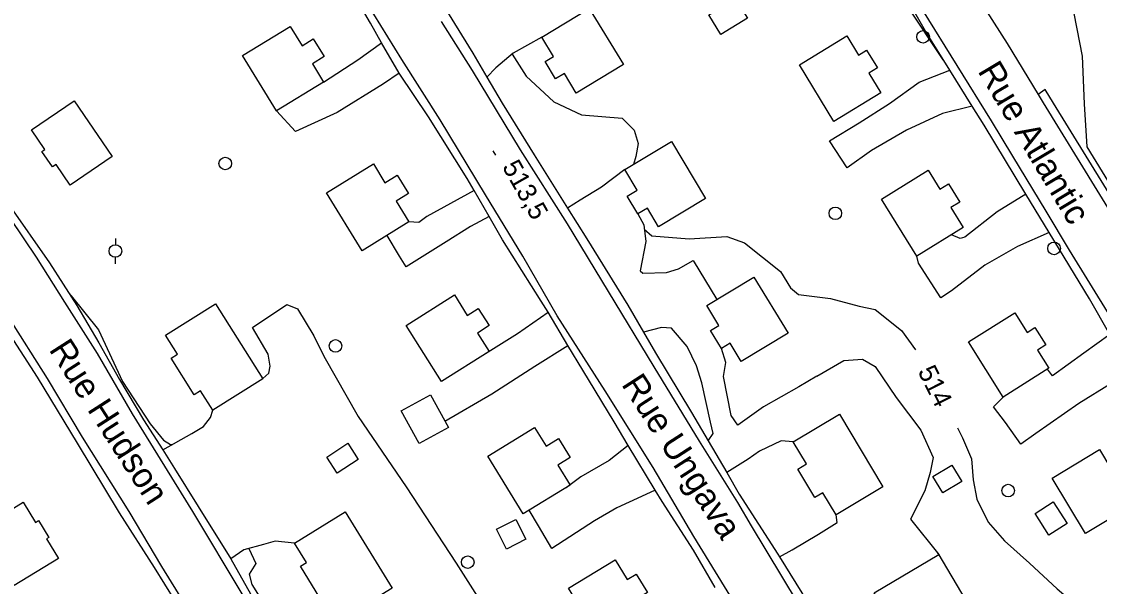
# Model space of a CAD drawing. Extents: x 347312 to 350503, y 6073086 to 6076432.
# Drawn here: x 348840.1 to 349011.5, y 6075247.2 to 6075337 of the extents above; entities that cross this region are included whole.
import ezdxf

# ---------------------------------------------------------------- set-up
doc = ezdxf.new("R2010")
doc.units = 0
for name, color, linetype in [('Level 19', 7, 'Continuous'), ('Level 2', 7, 'Continuous'), ('Level 21', 7, 'Continuous'), ('Level 22', 7, 'Continuous'), ('Level 3', 7, 'Continuous'), ('Level 31', 7, 'Continuous'), ('Level 36', 7, 'Continuous')]:
    doc.layers.add(name, color=color, linetype=linetype)

msp = doc.modelspace()

# ---------------------------------------------------------------- linework, layer by layer
at = {"layer": 'Level 19'}
for points in [[(348888.11, 6075327.41), (348893.54, 6075330.93), (348897.34, 6075333.66)], [(348922.85, 6075334.53), (348918.25, 6075332), (348915.53, 6075329.67), (348914.07, 6075328.19)], [(348900.13, 6075328.83), (348897.63, 6075327.14), (348890.29, 6075322.56), (348883.63, 6075319.53), (348880.6, 6075322.82)], [(348991.29, 6075323.54), (348986.57, 6075322.39), (348980.85, 6075319.76), (348975.28, 6075316.51), (348971.4, 6075313.75), (348968.58, 6075318.03), (348973.29, 6075320.9), (348978.11, 6075323.98), (348982.87, 6075327.4), (348987.73, 6075329.27)], [(348936.04, 6075313.47), (348932.33, 6075310.7), (348928.92, 6075308.63), (348926.93, 6075307.33)], [(348912.05, 6075310.13), (348904.55, 6075306.02), (348903.23, 6075305.08), (348901.69, 6075305.15)], [(348999.82, 6075309.57), (348995.28, 6075306.78), (348990.13, 6075302.74), (348989.36, 6075302.49), (348987.99, 6075303.11)], [(348914.43, 6075306.03), (348911.47, 6075304.44), (348907.58, 6075301.97), (348901.24, 6075298), (348900.19, 6075299.69), (348898.21, 6075303.01)], [(348938.1, 6075306.42), (348939.04, 6075304.68), (348939.38, 6075302.03), (348938.49, 6075297.38), (348938.91, 6075296.98), (348942.67, 6075297.08), (348944.58, 6075297.68)], [(349003.55, 6075303.47), (348998.51, 6075301.23), (348993.29, 6075298.27), (348987.97, 6075294.17), (348986.3, 6075293.09), (348982.77, 6075298.59), (348982.47, 6075299.69)], [(348944.58, 6075297.68), (348946.92, 6075299.02), (348950.65, 6075292.79)], [(348878.42, 6075280.24), (348879.37, 6075281.09), (348879.63, 6075282.22), (348879.27, 6075284.1), (348876.78, 6075288.36), (348882.27, 6075291.99), (348883.98, 6075291.3), (348886.55, 6075287.04), (348888.14, 6075283.77), (348893.6, 6075274.22), (348901.26, 6075263.03), (348909.2, 6075250.87), (348918.49, 6075236.28), (348922.42, 6075227.94), (348928.38, 6075219.24), (348931.71, 6075212.06), (348933.83, 6075202.37), (348933.43, 6075194.96), (348930.8, 6075186.08), (348926.25, 6075177.04), (348923.4, 6075172.49), (348915.69, 6075168.07), (348912.62, 6075164.78), (348908.07, 6075162)], [(348913.46, 6075283.94), (348918.93, 6075287.41), (348923.81, 6075290.77)], [(348949.27, 6075270.34), (348950.07, 6075271.51), (348949.66, 6075273.28), (348948.26, 6075279.57), (348947.44, 6075282.27), (348945.95, 6075285.33), (348943.46, 6075288.23), (348941.87, 6075288.36), (348938.99, 6075287.64)], [(349013.18, 6075287.26), (349009.04, 6075284.26), (349004.09, 6075280.69), (349003.25, 6075281.73)], [(348907.41, 6075273.44), (348914.86, 6075277.8), (348921.73, 6075282.21), (348926.98, 6075285.49)], [(348966.58, 6075280.62), (348963.7, 6075278.92), (348958.09, 6075275.71), (348954.03, 6075272.8), (348952.96, 6075274.36), (348951.72, 6075280.55), (348952.09, 6075282.81), (348951.4, 6075285.02)], [(348966.58, 6075280.62), (348970.85, 6075283.1), (348973.83, 6075283.32), (348975.87, 6075282.14), (348979.21, 6075277.23), (348983.1, 6075272.02), (348985.08, 6075267.65), (348984.62, 6075265.31), (348983.77, 6075262.35), (348981.46, 6075257.88), (348985.97, 6075252.22)], [(349016.71, 6075281.66), (349013.42, 6075279.47), (349008.26, 6075276.26), (349001.39, 6075271.48), (348999.01, 6075269.81), (348996.61, 6075273.24), (348994.69, 6075275.71), (348996.2, 6075277.29)], [(348862.52, 6075268.89), (348867.13, 6075271.51), (348869, 6075272.61), (348870.12, 6075274.06), (348870.48, 6075275.18)], [(348962.83, 6075270.17), (348960.91, 6075270.31), (348957.46, 6075268.66), (348955.65, 6075267.39), (348952.23, 6075265.28)], [(348936.57, 6075269.6), (348933.56, 6075267.2), (348929.03, 6075264.58), (348926.68, 6075262.87)], [(348940.88, 6075262.49), (348938.68, 6075261.48), (348934.76, 6075259.67), (348931.2, 6075257.62), (348924.4, 6075253.2), (348922.3, 6075256.83), (348920.82, 6075259.28)], [(348960.63, 6075251.88), (348962.67, 6075252.97), (348966.86, 6075255.46), (348969.82, 6075257.33), (348969.63, 6075258.57)], [(348883.5, 6075254.07), (348880.39, 6075254.36), (348878.57, 6075253.83), (348875.4, 6075253.01), (348873.34, 6075251.57)]]:
    msp.add_lwpolyline(points, dxfattribs=at)
at = {"layer": 'Level 2'}
for points in [[(348986.68, 6075330.96), (348980.99, 6075339.46), (348979.56, 6075342.26), (348976.88, 6075343.13), (348969.82, 6075341.2), (348969.21, 6075342.11), (348968.45, 6075345.12)], [(349019.19, 6075301.43), (349009.58, 6075317.1), (349009.15, 6075323.96), (349008.85, 6075331.54), (349007.09, 6075340.53)], [(348918.09, 6075331.86), (348920.33, 6075328.34), (348924.72, 6075324.24), (348929.15, 6075322.19), (348935.6, 6075321.67), (348937.49, 6075319.77), (348938.15, 6075317.62), (348937.76, 6075315.56), (348937.41, 6075314.3)], [(348939.13, 6075304.01), (348940.34, 6075302.96), (348946.27, 6075302.45), (348952.26, 6075302.83), (348955.04, 6075301.84), (348960.77, 6075297.26), (348962.4, 6075294.65), (348963.66, 6075293.59), (348968.76, 6075292.97), (348973.3, 6075291.74), (348975.83, 6075291.21), (348980.03, 6075287.86), (348982.26, 6075284.8)], [(348847.58, 6075293.83), (348847.97, 6075293.42), (348852.29, 6075287.96), (348856.11, 6075279.75), (348860.51, 6075273.01), (348862.66, 6075270.43), (348863.75, 6075269.75), (348864.05, 6075269.76)], [(348988.95, 6075272.39), (348989.77, 6075270.78), (348991.18, 6075267.47), (348991.45, 6075264.13), (348992.02, 6075261.04), (348993.83, 6075257.41), (348996.42, 6075254.43), (349000.39, 6075250.88), (349004.8, 6075246.79), (349008.32, 6075243.79)], [(348876.22, 6075253.22), (348877.34, 6075250.81), (348876.24, 6075249.14), (348876.7, 6075247.49), (348881.69, 6075239.5), (348882.29, 6075238.42), (348883.33, 6075237.99), (348886.25, 6075238.44)]]:
    msp.add_lwpolyline(points, dxfattribs=at)
at = {"layer": 'Level 21'}
for points in [[(348918.72, 6075462.7), (348918.85, 6075461.46), (348919.09, 6075460.45), (348925, 6075450.92), (348931.37, 6075440.49), (348941.67, 6075423.17), (348949.55, 6075408.65), (348954.25, 6075400.22), (348964.31, 6075385.54), (348971.97, 6075373.99), (348981.55, 6075358.54), (348988.67, 6075346.38), (348996.84, 6075333.51), (349001.76, 6075325.44), (349002.6, 6075324.07), (349011.14, 6075310.21), (349018.66, 6075297.93)], [(348975.65, 6075160.34), (348993.33, 6075171.28), (348994.88, 6075172.86), (348995.53, 6075174.07), (348995.35, 6075175.74), (348991.91, 6075181.78), (348984.39, 6075194.24), (348984.04, 6075194.81), (348981.76, 6075198.44), (348980.16, 6075201), (348977.99, 6075204.46), (348970.25, 6075217.11), (348963.34, 6075228.49), (348955.74, 6075240.87), (348947.03, 6075255.12), (348940.54, 6075266.08), (348932.89, 6075278.26), (348925.26, 6075290.22), (348919.79, 6075299.68), (348913.85, 6075309.44), (348906.67, 6075321.4), (348900.56, 6075331), (348895.01, 6075340.01)], [(349013.24, 6075290.17), (349006.75, 6075300.67), (349003.07, 6075306.88), (348997.74, 6075315.63), (348994.34, 6075321.24), (348983.44, 6075338.84)], [(348906.82, 6075337.06), (348911.74, 6075329.26), (348919.39, 6075316.64), (348926.87, 6075304.85), (348933.38, 6075294.06), (348940.64, 6075282.09), (348947.83, 6075270.29), (348953.94, 6075260.51), (348956.11, 6075256.82), (348963.44, 6075244.67), (348970.63, 6075233.14), (348978.06, 6075221.15), (348983.67, 6075211.33), (348986.33, 6075206.96), (348989.39, 6075201.95), (348990.27, 6075200.51), (348992.54, 6075196.69)], [(348836.11, 6075308.78), (348842.38, 6075299.53), (348846.88, 6075292.41), (348852.09, 6075284.24), (348857.63, 6075274.6), (348867.24, 6075259.07), (348875.25, 6075245.74), (348884.3, 6075230.78), (348892.05, 6075218.66), (348896.75, 6075210.12)], [(348837.63, 6075164.8), (348847.85, 6075169.11), (348859.97, 6075175.59), (348870.23, 6075181.75), (348881.79, 6075188.9), (348887.64, 6075193.21), (348889.24, 6075195.37), (348889.95, 6075197.23), (348890.56, 6075200.3), (348890.24, 6075203.5), (348889.5, 6075206.21), (348883.49, 6075215.78), (348878.56, 6075223.6), (348871, 6075236.32), (348862.36, 6075250.33), (348857.19, 6075259.08), (348849.75, 6075270.91), (348844.18, 6075280.23), (348837.85, 6075290.19)]]:
    msp.add_lwpolyline(points, dxfattribs=at)
at = {"layer": 'Level 22'}
for points in [[(348950.42, 6075247.02), (348946.93, 6075252.93), (348941.96, 6075260.7), (348940.88, 6075262.49), (348936.57, 6075269.6), (348934.31, 6075273.33), (348929.34, 6075281.56), (348926.98, 6075285.49), (348923.81, 6075290.77), (348922.73, 6075292.56), (348916.59, 6075302.29), (348914.43, 6075306.03), (348912.05, 6075310.13), (348910.94, 6075312.06), (348904.8, 6075321.86), (348900.13, 6075328.83), (348897.34, 6075333.66), (348895.56, 6075336.76), (348892.08, 6075342.83)], [(349013.18, 6075287.26), (349009.95, 6075292.9), (349003.55, 6075303.47), (348999.82, 6075309.57), (348993.17, 6075320.53), (348991.29, 6075323.54), (348987.73, 6075329.27), (348983.84, 6075335.52), (348979.44, 6075343.23)], [(348907.83, 6075338.53), (348911.84, 6075332), (348914.07, 6075328.19), (348916.5, 6075324.06), (348921.63, 6075315.82), (348926.93, 6075307.33), (348929.99, 6075302.44), (348936.48, 6075291.93), (348938.99, 6075287.64), (348940.93, 6075284.33), (348946.65, 6075274.84), (348949.27, 6075270.34), (348952.23, 6075265.28), (348954.23, 6075261.85), (348960.36, 6075252.32), (348960.63, 6075251.88), (348965.81, 6075243.51)], [(349068.85, 6075218.36), (349064.51, 6075225.75), (349057.94, 6075236.35), (349050.48, 6075248.55), (349043.67, 6075259.62), (349037.01, 6075270.29), (349028.28, 6075284.66), (349019.88, 6075298.63), (349012.24, 6075311.04), (349004.2, 6075324.02), (349002.92, 6075326.2), (349001.76, 6075325.44)], [(348838, 6075307.97), (348844.48, 6075298.66), (348848.87, 6075291.84), (348852.36, 6075285.92), (348855.62, 6075280.11), (348859.47, 6075273.67), (348862.52, 6075268.89), (348864.4, 6075265.93), (348868.17, 6075259.87), (348873.34, 6075251.57), (348878.41, 6075242.59), (348881.94, 6075237.07)], [(348867.76, 6075239.56), (348861.2, 6075250.16), (348855.62, 6075258.87), (348848.93, 6075269.97), (348842.61, 6075280.47), (348833.95, 6075293.77)]]:
    msp.add_lwpolyline(points, dxfattribs=at)
at = {"layer": 'Level 3'}
msp.add_line((348915.05, 6075316.46), (348915.44, 6075315.76), dxfattribs=at)
at = {"layer": 'Level 31'}
for points in [[(348955.52, 6075337.59), (348951.3, 6075334.99), (348949.38, 6075338.11), (348953.6, 6075340.71), (348955.52, 6075337.59)], [(348930.37, 6075339.09), (348935.79, 6075330.17), (348928.3, 6075325.63), (348926.41, 6075328.75), (348925.01, 6075327.9), (348923.34, 6075330.65), (348924.7, 6075331.48), (348922.85, 6075334.53), (348930.37, 6075339.09)], [(348880.6, 6075322.82), (348875.22, 6075331.62), (348882.79, 6075336.25), (348884.67, 6075333.17), (348886.45, 6075334.27), (348888.17, 6075331.45), (348886.33, 6075330.32), (348888.11, 6075327.41), (348880.6, 6075322.82)], [(348969.29, 6075321.13), (348963.8, 6075330.15), (348971.33, 6075334.73), (348973.19, 6075331.69), (348974.49, 6075332.48), (348976.2, 6075329.66), (348974.85, 6075328.83), (348976.76, 6075325.68), (348969.29, 6075321.13)], [(348848.45, 6075324.43), (348854.49, 6075315.56), (348847.79, 6075311.01), (348845.56, 6075314.29), (348844.98, 6075313.9), (348843.3, 6075316.37), (348843.78, 6075316.69), (348841.66, 6075319.81), (348848.45, 6075324.43)], [(348943.44, 6075317.92), (348948.88, 6075308.86), (348941.4, 6075304.37), (348939.62, 6075307.33), (348938.1, 6075306.42), (348936.41, 6075309.23), (348938.01, 6075310.19), (348936.04, 6075313.47), (348943.44, 6075317.92)], [(348894.22, 6075300.56), (348888.55, 6075309.8), (348896.03, 6075314.39), (348897.87, 6075311.39), (348899.81, 6075312.58), (348901.6, 6075309.65), (348899.66, 6075308.46), (348901.69, 6075305.15), (348894.22, 6075300.56)], [(348982.47, 6075299.69), (348976.86, 6075308.76), (348984.3, 6075313.36), (348986.16, 6075310.36), (348987.51, 6075311.2), (348989.3, 6075308.31), (348987.89, 6075307.45), (348989.86, 6075304.26), (348982.47, 6075299.69)], [(348956.57, 6075296.38), (348961.99, 6075287.45), (348954.55, 6075282.94), (348952.78, 6075285.86), (348951.4, 6075285.02), (348949.67, 6075287.88), (348951, 6075288.68), (348949.08, 6075291.84), (348956.57, 6075296.38)], [(348870.92, 6075292.12), (348878.44, 6075280.2), (348870.48, 6075275.18), (348868.54, 6075278.26), (348867.54, 6075277.63), (348863.84, 6075283.49), (348864.86, 6075284.13), (348862.98, 6075287.12), (348870.92, 6075292.12)], [(348906.87, 6075279.78), (348901.25, 6075288.69), (348908.91, 6075293.53), (348910.96, 6075290.28), (348912.72, 6075291.4), (348914.45, 6075288.66), (348912.57, 6075287.48), (348914.42, 6075284.55), (348906.87, 6075279.78)], [(348996.2, 6075277.29), (348990.68, 6075286.07), (348998.05, 6075290.7), (349000.02, 6075287.56), (349001.28, 6075288.34), (349002.99, 6075285.61), (349001.66, 6075284.77), (349003.48, 6075281.87), (348996.2, 6075277.29)], [(348900.46, 6075275.08), (348905.09, 6075277.64), (348907.96, 6075272.44), (348903.33, 6075269.88), (348900.46, 6075275.08)], [(348970.17, 6075274.57), (348977.07, 6075263.03), (348969.63, 6075258.57), (348967.53, 6075262.07), (348966.26, 6075261.31), (348963.56, 6075265.83), (348964.94, 6075266.66), (348962.83, 6075270.17), (348970.17, 6075274.57)], [(348919.87, 6075258.7), (348914.24, 6075267.91), (348921.68, 6075272.46), (348923.51, 6075269.47), (348925.47, 6075270.68), (348927.32, 6075267.65), (348925.37, 6075266.46), (348927.33, 6075263.27), (348919.87, 6075258.7)], [(348888.6, 6075267.74), (348891.97, 6075269.93), (348893.63, 6075267.38), (348890.26, 6075265.19), (348888.6, 6075267.74)], [(349009.33, 6075255.56), (349003.99, 6075264.4), (349011.53, 6075268.96), (349013.37, 6075265.9), (349014.7, 6075266.7), (349016.43, 6075263.84), (349015.13, 6075263.06), (349016.9, 6075260.13), (349009.33, 6075255.56)], [(348989.62, 6075263.84), (348986.61, 6075262.03), (348985.04, 6075264.64), (348988.05, 6075266.45), (348989.62, 6075263.84)], [(348838.89, 6075247.31), (348833.4, 6075256.34), (348840.32, 6075260.55), (348842.27, 6075257.35), (348842.74, 6075257.64), (348844.38, 6075254.93), (348844.03, 6075254.72), (348845.93, 6075251.59), (348838.89, 6075247.31)], [(349003.48, 6075255.34), (349001.29, 6075258.78), (349004.19, 6075260.62), (349006.38, 6075257.18), (349003.48, 6075255.34)], [(348891.56, 6075259.03), (348899.03, 6075246.9), (348891.06, 6075242), (348889.18, 6075245.06), (348888.11, 6075244.4), (348884.42, 6075250.39), (348885.39, 6075250.99), (348883.5, 6075254.07), (348891.56, 6075259.03)], [(348915.61, 6075256.25), (348918.67, 6075257.81), (348920.27, 6075254.67), (348917.21, 6075253.11), (348915.61, 6075256.25)], [(348932.57, 6075237.87), (348927.08, 6075246.9), (348934.5, 6075251.41), (348936.41, 6075248.28), (348937.82, 6075249.14), (348939.62, 6075246.19), (348938.13, 6075245.28), (348939.92, 6075242.34), (348932.57, 6075237.87)], [(348985.84, 6075252.44), (348990.28, 6075244.95), (348981.37, 6075239.66), (348978.71, 6075244.15), (348977.37, 6075243.36), (348975.72, 6075246.14), (348985.97, 6075252.22), (348985.84, 6075252.44)]]:
    msp.add_lwpolyline(points, dxfattribs=at)
at = {"layer": 'Level 36'}
for p, q in [((348854.99, 6075302.51), (348854.99, 6075301.51)), ((348854.99, 6075298.51), (348854.99, 6075299.51))]:
    msp.add_line(p, q, dxfattribs=at)
for centre in [(348983.48, 6075334.6), (348872.46, 6075314.45), (348969.51, 6075306.52), (348854.99, 6075300.52), (349004.32, 6075300.94), (348890, 6075285.43), (348997.01, 6075262.41), (348911.04, 6075251.02)]:
    msp.add_circle(centre, 1, dxfattribs=at)

# ---------------------------------------------------------------- texts
at = {"layer": 'Level 2'}
msp.add_text('514', height=3, rotation=296.6185, dxfattribs=at).set_placement((348982.57, 6075281.39))
at = {"layer": 'Level 21'}
for s, rotation, p in [('Rue Atlantic', 300.8434, (348992.08, 6075329.16)), ('Rue Hudson', 302.6656, (348844.31, 6075284.85)), ('Rue Ungava', 302.826, (348935.39, 6075279.31))]:
    msp.add_text(s, height=4, rotation=rotation, dxfattribs=at).set_placement(p)
at = {"layer": 'Level 3'}
msp.add_text('513,5', height=3, rotation=299.56, dxfattribs=at).set_placement((348916.44, 6075313.93))

doc.saveas('drawing.dxf')
